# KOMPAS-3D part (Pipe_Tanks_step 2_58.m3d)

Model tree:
1. X Axis
2. Y Axis
3. Z Axis  (labels: Valve Dy 50; Pipe Dn 50)
     Òîëùèíà ñòåíêè 1 = 1

Referenced files in C:\Documents and Settings\kashirsky\Мои документы\Camtasia Studio\Pipelines3D\Tanks\: Tanks_step 2.a3d
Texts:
  Pipe Dn 50
  Steel ASTM A295
  Three Point Plane
  Plane at Angle
  Line and Point Plane
  Axis through Two Vertices
  Axis of Feature
  Axis of Conical Surface
  Axis through Edge
  Trim by Surface
  Trim by Sketch
  Feature with No History
  Intersection Axis of Two Planes
  Two Line Plane
  Line and Face Plane
  Bend by line
  Hole in sheet body
  Cut in sheet body
  Point in CM
  Linear Dimension from Line to Point
  Surface Finish Symbol
  Geometric Tolerance Symbol
  Leader #1
  Leader #2
  Leader #3
  Shape Deviations and Datum
  Node point number
  Mark of coordination axis
  Node point designation
  Mark/Reference designation with leader
  Mark/reference designation on line
  Mark/Reference designation without leader
  Valve Dy 50
  Plane of section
